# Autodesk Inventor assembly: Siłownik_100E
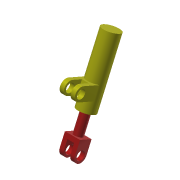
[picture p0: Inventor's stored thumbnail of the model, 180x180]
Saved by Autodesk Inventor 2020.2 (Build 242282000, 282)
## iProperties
Created: 2005-10
Part Number: Siłownik_100E
Document SubType Name: Assembly
Designer: F.Stasiak
Manager: www.cadconsulting.pl
Company: Fabian Stasiak CAD Consulting
Author: F.Stasiak
Subject: Zbiór ćwiczeń. Autodesk Inventor 2020. Kurs podstawowy
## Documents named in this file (3)
- C:\2020_Kurs_podstawowy\R6 Zespoły\Elastyczne\Siłownik_100E.iam
- C:\2020_Kurs_podstawowy\R6 Zespoły\Elastyczne\Tłoczek_100E.ipt
- C:\2020_Kurs_podstawowy\R6 Zespoły\Elastyczne\Cylinder_100E.ipt
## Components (2 placed, 2 different names)
1. Cylinder_100E:1 — WYSUNIĘCIE TŁOCZKA
2. Tłoczek_100E:1 — WYSUNIĘCIE TŁOCZKA
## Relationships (1: Mate 1)
- WYSUNIĘCIE TŁOCZKA [Mate]: Cylinder_100E:1 ↔ Tłoczek_100E:1
